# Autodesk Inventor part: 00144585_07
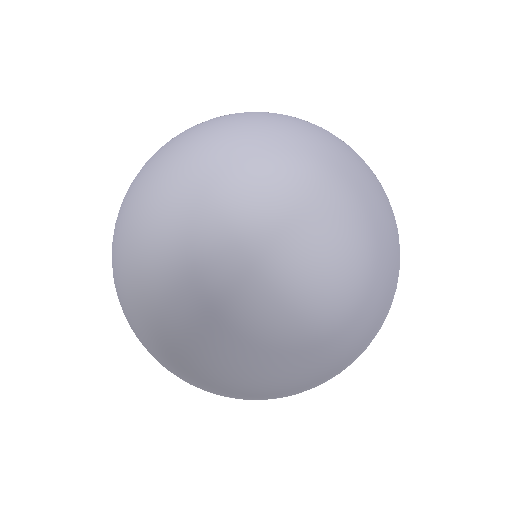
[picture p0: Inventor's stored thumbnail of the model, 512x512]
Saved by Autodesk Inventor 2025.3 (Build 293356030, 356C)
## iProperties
Created: 2021-02
Part Number: 00144585_07
Material: Generico
Document SubType Name: Modeling
Designer: R5800u
Density: 1 g/cm^3
Appearance: Default
Author: TraceParts
Sending System: SolidWorks 2021
Last Author: Albert
Last Saved: 2021-07-28
IsFastener: 1
TYPE: CATASM
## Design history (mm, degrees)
feature "Imported1"
node "Solido1"
